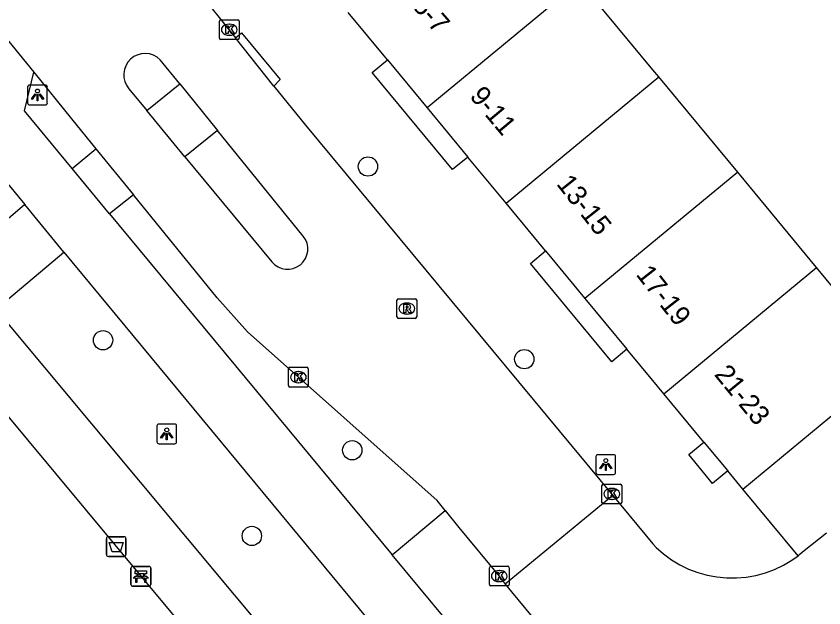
# Model space of a CAD drawing. Extents: x 159280 to 160375, y 384531 to 385872.
# Drawn here: x 159467.75 to 159508.65, y 385108.51 to 385138.49 of the extents above; entities that cross this region are included whole.
import ezdxf

# ---------------------------------------------------------------- set-up
doc = ezdxf.new("R2010")
doc.units = 0
for name, color, linetype in [('IMGEO_Afvalbak', 7, 'Continuous'), ('IMGEO_Bank', 7, 'Continuous'), ('IMGEO_Boom', 7, 'Continuous'), ('IMGEO_Fietspad_open', 7, 'Continuous'), ('IMGEO_Haag', 7, 'Continuous'), ('IMGEO_Kolk', 7, 'Continuous'), ('IMGEO_Lichtpunt', 7, 'Continuous'), ('IMGEO_Pand', 7, 'Continuous'), ('IMGEO_Pand_nummerreeks', 7, 'Continuous'), ('IMGEO_Rijbaan_lokaal_open', 7, 'Continuous'), ('IMGEO_Rioolput', 7, 'Continuous'), ('IMGEO_Voetpad_halfverhard', 7, 'Continuous'), ('IMGEO_Voetpad_open', 7, 'Continuous')]:
    doc.layers.add(name, color=color, linetype=linetype)

msp = doc.modelspace()

# ---------------------------------------------------------------- linework, layer by layer
at = {"layer": 'IMGEO_Afvalbak'}
for p, q in [((159472.423, 385112.112), (159473.213, 385112.112)), ((159473.213, 385112.112), (159472.423, 385112.112)), ((159472.323, 385111.212), (159472.323, 385112.012)), ((159472.323, 385112.012), (159472.323, 385111.212)), ((159473.313, 385112.012), (159473.313, 385111.212)), ((159473.313, 385111.212), (159473.313, 385112.012)), ((159473.213, 385111.112), (159472.423, 385111.112)), ((159472.423, 385111.112), (159473.213, 385111.112))]:
    msp.add_line(p, q, dxfattribs=at)
msp.add_lwpolyline([(159472.466, 385111.826), (159473.17, 385111.826), (159473.021, 385111.356), (159472.615, 385111.356), (159472.466, 385111.826)], dxfattribs=at)
for centre, start, end in [((159472.423, 385112.012), 90, 180), ((159472.423, 385112.012), 90, 180), ((159473.213, 385112.012), 0, 90), ((159473.213, 385112.012), 360, 90), ((159472.423, 385111.212), 180, 270), ((159472.423, 385111.212), 180, 270), ((159473.213, 385111.212), 270, 0), ((159473.213, 385111.212), 270, 0)]:
    msp.add_arc(centre, 0.1, start, end, dxfattribs=at)
at = {"layer": 'IMGEO_Bank'}
for p, q in [((159473.568, 385109.685), (159473.568, 385110.526)), ((159473.568, 385110.526), (159473.568, 385109.685)), ((159473.643, 385110.61), (159474.484, 385110.61)), ((159474.484, 385110.61), (159473.643, 385110.61)), ((159474.568, 385110.535), (159474.568, 385109.694)), ((159474.568, 385109.694), (159474.568, 385110.535)), ((159473.877, 385110.116), (159473.877, 385110.222)), ((159473.921, 385110.222), (159473.921, 385110.116)), ((159474.209, 385110.228), (159473.927, 385110.228)), ((159473.927, 385110.11), (159474.209, 385110.11)), ((159474.215, 385110.116), (159474.215, 385110.222)), ((159474.259, 385110.222), (159474.259, 385110.116)), ((159474.493, 385109.61), (159473.652, 385109.61)), ((159473.652, 385109.61), (159474.493, 385109.61)), ((159474.265, 385110.008), (159473.872, 385110.008))]:
    msp.add_line(p, q, dxfattribs=at)
for points in [[(159473.815, 385110.008), (159473.673, 385110.008), (159473.785, 385110.11), (159473.871, 385110.11)], [(159473.871, 385110.228), (159473.785, 385110.228), (159473.785, 385110.389), (159474.348, 385110.389), (159474.348, 385110.228), (159474.265, 385110.228)], [(159474.265, 385110.11), (159474.348, 385110.11), (159474.46, 385110.008), (159474.321, 385110.008)], [(159473.865, 385110.001), (159473.865, 385109.794), (159473.822, 385109.794), (159473.822, 385110.001)], [(159474.315, 385110.001), (159474.315, 385109.794), (159474.271, 385109.794), (159474.271, 385110.001)]]:
    msp.add_lwpolyline(points, dxfattribs=at)
for centre, radius, start, end in [((159473.646, 385110.532), 0.0779, 92.4484, 184.2845), ((159473.646, 385110.532), 0.0779, 92.4484, 184.2845), ((159474.49, 385110.532), 0.0779, 2.4484, 94.2845), ((159474.49, 385110.532), 0.0779, 2.4484, 94.2845), ((159473.87, 385110.221), 0.00671, 2.8957, 87.1043), ((159473.87, 385110.117), 0.00671, 272.8957, 357.1043), ((159473.927, 385110.221), 0.00671, 92.8957, 177.1043), ((159473.927, 385110.117), 0.00671, 182.8957, 267.1043), ((159474.209, 385110.221), 0.00671, 2.8957, 87.1043), ((159474.209, 385110.117), 0.00671, 272.8957, 357.1043), ((159474.266, 385110.221), 0.00671, 92.8957, 177.1043), ((159474.266, 385110.117), 0.00671, 182.8957, 267.1043), ((159473.646, 385109.688), 0.0779, 182.4484, 274.2845), ((159473.646, 385109.688), 0.0779, 182.4484, 274.2845), ((159473.815, 385110.001), 0.00671, 2.8957, 87.1043), ((159473.872, 385110.001), 0.00671, 92.8957, 177.1043), ((159474.264, 385110.001), 0.00671, 2.8957, 87.1043), ((159474.321, 385110.001), 0.00671, 92.8957, 177.1043), ((159474.49, 385109.688), 0.0779, 272.4484, 4.2845), ((159474.49, 385109.688), 0.0779, 272.4484, 4.2845)]:
    msp.add_arc(centre, radius, start, end, dxfattribs=at)
at = {"layer": 'IMGEO_Boom'}
for centre in [(159485.569, 385130.873), (159472.153, 385122.07), (159493.486, 385121.11), (159484.773, 385116.495), (159479.69, 385112.153)]:
    msp.add_circle(centre, 0.489, dxfattribs=at)
at = {"layer": 'IMGEO_Fietspad_open'}
for points in [[(159405.443, 385221.27), (159417.105, 385196.774), (159421.543, 385188.209), (159424.758, 385182.98), (159430.05, 385175.255), (159434.187, 385170.106), (159442.865, 385159.598), (159444.527, 385157.561), (159454.301, 385145.739), (159456.65, 385142.935), (159463.095, 385135.058), (159465.215, 385132.533), (159468.191, 385128.94)], [(159470.596, 385130.776), (159468.169, 385133.7), (159468.656, 385135.65)], [(159472.473, 385128.474), (159470.596, 385130.776)], [(159470.17, 385126.528), (159468.191, 385128.94)], [(159472.473, 385128.474), (159486.797, 385111.202)], [(159470.17, 385126.528), (159494.306, 385097.36)], [(159499.271, 385101.533), (159496.605, 385099.375), (159486.797, 385111.202)]]:
    msp.add_lwpolyline(points, dxfattribs=at)
at = {"layer": 'IMGEO_Haag'}
msp.add_lwpolyline([(159486.797, 385111.202), (159489.484, 385113.434)], dxfattribs=at)
at = {"layer": 'IMGEO_Kolk'}
for p, q in [((159478.122, 385138.306), (159478.974, 385138.306)), ((159478.047, 385137.38), (159478.047, 385138.232)), ((159478.535, 385138.086), (159478.56, 385138.086)), ((159479.048, 385138.232), (159479.048, 385137.38)), ((159478.558, 385137.526), (159478.533, 385137.526)), ((159478.974, 385137.306), (159478.122, 385137.306)), ((159481.618, 385120.699), (159482.47, 385120.699)), ((159481.543, 385119.773), (159481.543, 385120.625)), ((159482.031, 385120.479), (159482.056, 385120.479)), ((159482.544, 385120.625), (159482.544, 385119.773)), ((159482.054, 385119.919), (159482.029, 385119.919)), ((159482.47, 385119.699), (159481.618, 385119.699)), ((159497.416, 385113.856), (159497.416, 385114.708)), ((159497.491, 385114.782), (159498.343, 385114.782)), ((159497.904, 385114.562), (159497.929, 385114.562)), ((159498.417, 385114.708), (159498.417, 385113.856)), ((159498.343, 385113.782), (159497.491, 385113.782)), ((159497.927, 385114.002), (159497.902, 385114.002)), ((159491.717, 385109.693), (159491.717, 385110.545)), ((159491.792, 385110.619), (159492.644, 385110.619)), ((159492.718, 385110.545), (159492.718, 385109.693)), ((159492.205, 385110.399), (159492.23, 385110.399)), ((159492.644, 385109.619), (159491.792, 385109.619)), ((159492.228, 385109.839), (159492.203, 385109.839))]:
    msp.add_line(p, q, dxfattribs=at)
for points in [[(159478.122, 385138.306), (159478.974, 385138.306)], [(159478.047, 385137.38), (159478.047, 385138.232)], [(159478.368, 385138.006), (159478.491, 385138.006), (159478.491, 385137.855), (159478.621, 385138.006), (159478.785, 385138.006), (159478.639, 385137.855), (159478.792, 385137.606), (159478.64, 385137.606), (159478.555, 385137.77), (159478.491, 385137.703), (159478.491, 385137.606), (159478.368, 385137.606), (159478.368, 385138.006)], [(159479.048, 385138.232), (159479.048, 385137.38)], [(159478.974, 385137.306), (159478.122, 385137.306)], [(159481.618, 385120.699), (159482.47, 385120.699)], [(159481.543, 385119.773), (159481.543, 385120.625)], [(159481.864, 385120.399), (159481.987, 385120.399), (159481.987, 385120.248), (159482.117, 385120.399), (159482.281, 385120.399), (159482.135, 385120.248), (159482.288, 385119.999), (159482.136, 385119.999), (159482.051, 385120.163), (159481.987, 385120.096), (159481.987, 385119.999), (159481.864, 385119.999), (159481.864, 385120.399)], [(159482.544, 385120.625), (159482.544, 385119.773)], [(159482.47, 385119.699), (159481.618, 385119.699)], [(159497.416, 385113.856), (159497.416, 385114.708)], [(159497.491, 385114.782), (159498.343, 385114.782)], [(159498.417, 385114.708), (159498.417, 385113.856)], [(159497.737, 385114.482), (159497.86, 385114.482), (159497.86, 385114.331), (159497.99, 385114.482), (159498.154, 385114.482), (159498.008, 385114.331), (159498.161, 385114.082), (159498.009, 385114.082), (159497.924, 385114.246), (159497.86, 385114.179), (159497.86, 385114.082), (159497.737, 385114.082), (159497.737, 385114.482)], [(159498.343, 385113.782), (159497.491, 385113.782)], [(159491.717, 385109.693), (159491.717, 385110.545)], [(159491.792, 385110.619), (159492.644, 385110.619)], [(159492.718, 385110.545), (159492.718, 385109.693)], [(159492.038, 385110.319), (159492.161, 385110.319), (159492.161, 385110.168), (159492.291, 385110.319), (159492.455, 385110.319), (159492.309, 385110.168), (159492.462, 385109.919), (159492.31, 385109.919), (159492.225, 385110.083), (159492.161, 385110.016), (159492.161, 385109.919), (159492.038, 385109.919), (159492.038, 385110.319)], [(159492.644, 385109.619), (159491.792, 385109.619)]]:
    msp.add_lwpolyline(points, dxfattribs=at)
for centre, start, end in [((159478.124, 385138.23), 91.552, 178.448), ((159478.124, 385138.23), 91.552, 178.448), ((159478.972, 385138.23), 1.552, 88.448), ((159478.972, 385138.23), 1.552, 88.448), ((159478.124, 385137.382), 181.552, 268.448), ((159478.124, 385137.382), 181.552, 268.448), ((159478.972, 385137.382), 271.552, 358.448), ((159478.972, 385137.382), 271.552, 358.448), ((159481.62, 385120.623), 91.552, 178.448), ((159481.62, 385120.623), 91.552, 178.448), ((159482.468, 385120.623), 1.552, 88.448), ((159482.468, 385120.623), 1.552, 88.448), ((159481.62, 385119.775), 181.552, 268.448), ((159481.62, 385119.775), 181.552, 268.448), ((159482.468, 385119.775), 271.552, 358.448), ((159482.468, 385119.775), 271.552, 358.448), ((159497.493, 385114.706), 91.552, 178.448), ((159497.493, 385114.706), 91.552, 178.448), ((159498.341, 385114.706), 1.552, 88.448), ((159498.341, 385114.706), 1.552, 88.448), ((159497.493, 385113.858), 181.552, 268.448), ((159497.493, 385113.858), 181.552, 268.448), ((159498.341, 385113.858), 271.552, 358.448), ((159498.341, 385113.858), 271.552, 358.448), ((159491.794, 385110.543), 91.552, 178.448), ((159491.794, 385110.543), 91.552, 178.448), ((159492.642, 385110.543), 1.552, 88.448), ((159492.642, 385110.543), 1.552, 88.448), ((159491.794, 385109.695), 181.552, 268.448), ((159491.794, 385109.695), 181.552, 268.448), ((159492.642, 385109.695), 271.552, 358.448), ((159492.642, 385109.695), 271.552, 358.448)]:
    msp.add_arc(centre, 0.0765, start, end, dxfattribs=at)
for centre, major_axis, ratio, start_param, end_param in [((159478.534, 385137.806), (-0.387, 0.002), 0.722429, 4.712389, 7.853982), ((159478.559, 385137.806), (-0.39, 0.002), 0.717154, 1.570796, 4.712389), ((159482.03, 385120.199), (-0.387, 0.002), 0.722429, 4.712389, 7.853982), ((159482.055, 385120.199), (-0.39, 0.002), 0.717154, 1.570796, 4.712389), ((159497.903, 385114.282), (-0.387, 0.002), 0.722429, 4.712389, 7.853982), ((159497.928, 385114.282), (-0.39, 0.002), 0.717154, 1.570796, 4.712389), ((159492.204, 385110.119), (-0.387, 0.002), 0.722429, 4.712389, 7.853982), ((159492.229, 385110.119), (-0.39, 0.002), 0.717154, 1.570796, 4.712389)]:
    msp.add_ellipse(centre, major_axis=major_axis, ratio=ratio, start_param=start_param, end_param=end_param, dxfattribs=at)
at = {"layer": 'IMGEO_Lichtpunt'}
for p, q in [((159469.238, 385134.995), (159468.43, 385134.995)), ((159469.238, 385134.995), (159468.43, 385134.995)), ((159468.336, 385134.9), (159468.336, 385134.093)), ((159468.336, 385134.9), (159468.336, 385134.093)), ((159469.332, 385134.093), (159469.332, 385134.9)), ((159469.332, 385134.093), (159469.332, 385134.9)), ((159468.43, 385133.999), (159469.238, 385133.999)), ((159468.43, 385133.999), (159469.238, 385133.999)), ((159475.784, 385117.822), (159474.976, 385117.822)), ((159475.784, 385117.822), (159474.976, 385117.822)), ((159474.882, 385117.727), (159474.882, 385116.92)), ((159474.882, 385117.727), (159474.882, 385116.92)), ((159475.878, 385116.92), (159475.878, 385117.727)), ((159475.878, 385116.92), (159475.878, 385117.727)), ((159474.976, 385116.826), (159475.784, 385116.826)), ((159474.976, 385116.826), (159475.784, 385116.826)), ((159497.115, 385116.176), (159497.115, 385115.369)), ((159497.115, 385116.176), (159497.115, 385115.369)), ((159498.017, 385116.271), (159497.209, 385116.271)), ((159498.017, 385116.271), (159497.209, 385116.271)), ((159498.111, 385115.369), (159498.111, 385116.176)), ((159498.111, 385115.369), (159498.111, 385116.176)), ((159497.209, 385115.275), (159498.017, 385115.275)), ((159497.209, 385115.275), (159498.017, 385115.275))]:
    msp.add_line(p, q, dxfattribs=at)
for points in [[(159468.71, 385134.564), (159468.749, 385134.536), (159468.561, 385134.274), (159468.523, 385134.301), (159468.71, 385134.564)], [(159468.922, 385134.536), (159468.96, 385134.563), (159469.147, 385134.301), (159469.108, 385134.273), (159468.922, 385134.536)], [(159468.812, 385134.516), (159468.859, 385134.516), (159468.859, 385134.194), (159468.812, 385134.194), (159468.812, 385134.516)], [(159475.256, 385117.391), (159475.295, 385117.363), (159475.107, 385117.101), (159475.069, 385117.128), (159475.256, 385117.391)], [(159475.468, 385117.363), (159475.506, 385117.39), (159475.693, 385117.128), (159475.654, 385117.1), (159475.468, 385117.363)], [(159475.358, 385117.343), (159475.405, 385117.343), (159475.405, 385117.021), (159475.358, 385117.021), (159475.358, 385117.343)], [(159497.489, 385115.84), (159497.528, 385115.812), (159497.34, 385115.55), (159497.302, 385115.577), (159497.489, 385115.84)], [(159497.591, 385115.792), (159497.638, 385115.792), (159497.638, 385115.47), (159497.591, 385115.47), (159497.591, 385115.792)], [(159497.701, 385115.812), (159497.739, 385115.839), (159497.926, 385115.577), (159497.887, 385115.549), (159497.701, 385115.812)]]:
    msp.add_lwpolyline(points, dxfattribs=at)
for centre in [(159468.835, 385134.698), (159475.381, 385117.525), (159497.614, 385115.974)]:
    msp.add_circle(centre, 0.0994, dxfattribs=at)
for centre, start, end in [((159468.43, 385134.9), 90, 180), ((159468.43, 385134.9), 90, 180), ((159469.238, 385134.9), 0, 90), ((159469.238, 385134.9), 0, 90), ((159468.43, 385134.093), 180, 270), ((159468.43, 385134.093), 180, 270), ((159469.238, 385134.093), 270, 0), ((159469.238, 385134.093), 270, 360), ((159474.976, 385117.727), 90, 180), ((159474.976, 385117.727), 90, 180), ((159475.784, 385117.727), 0, 90), ((159475.784, 385117.727), 0, 90), ((159474.976, 385116.92), 180, 270), ((159474.976, 385116.92), 180, 270), ((159475.784, 385116.92), 270, 0), ((159475.784, 385116.92), 270, 360), ((159497.209, 385116.176), 90, 180), ((159497.209, 385116.176), 90, 180), ((159498.017, 385116.176), 0, 90), ((159498.017, 385116.176), 0, 90), ((159497.209, 385115.369), 180, 270), ((159497.209, 385115.369), 180, 270), ((159498.017, 385115.369), 270, 0), ((159498.017, 385115.369), 270, 360)]:
    msp.add_arc(centre, 0.0946, start, end, dxfattribs=at)
at = {"layer": 'IMGEO_Pand'}
for points in [[(159496.296, 385140.25), (159488.561, 385133.849)], [(159500.294, 385135.42), (159500, 385135.775), (159496.296, 385140.25)], [(159486.552, 385136.277), (159484.564, 385138.679)], [(159486.552, 385136.277), (159488.561, 385133.849)], [(159492.559, 385129.019), (159500.294, 385135.42)], [(159504.291, 385130.59), (159500.294, 385135.42)], [(159488.561, 385133.849), (159490.626, 385131.354)], [(159492.559, 385129.019), (159490.626, 385131.354)], [(159504.291, 385130.59), (159496.556, 385124.189)], [(159508.288, 385125.76), (159504.291, 385130.59)], [(159494.566, 385126.593), (159492.559, 385129.019)], [(159494.566, 385126.593), (159496.556, 385124.189)], [(159500.553, 385119.359), (159508.288, 385125.76)], [(159509.932, 385118.983), (159512.285, 385120.93), (159508.288, 385125.76)], [(159496.556, 385124.189), (159498.685, 385121.616)], [(159500.553, 385119.359), (159500, 385120.027), (159498.685, 385121.616)], [(159502.58, 385116.909), (159500.553, 385119.359)], [(159504.55, 385114.528), (159509.932, 385118.983)], [(159502.58, 385116.909), (159503.785, 385115.453)], [(159504.55, 385114.528), (159503.785, 385115.453)]]:
    msp.add_lwpolyline(points, dxfattribs=at)
at = {"layer": 'IMGEO_Rijbaan_lokaal_open'}
for points in [[(159476.853, 385139.918), (159478.861, 385137.393)], [(159466.777, 385137.938), (159468.656, 385135.65)], [(159480.804, 385134.95), (159478.861, 385137.393)], [(159476.044, 385135.056), (159475.053, 385136.278)], [(159468.656, 385135.65), (159470.552, 385133.285), (159471.786, 385131.774)], [(159476.044, 385135.056), (159477.948, 385132.706)], [(159473.462, 385134.813), (159474.367, 385133.716)], [(159480.804, 385134.95), (159482.4, 385132.975), (159497.976, 385114.2)], [(159476.303, 385131.369), (159474.367, 385133.716)], [(159482.295, 385127.343), (159477.948, 385132.706)], [(159471.786, 385131.774), (159473.693, 385129.437)], [(159476.303, 385131.369), (159480.7, 385126.039)], [(159489.484, 385113.434), (159489.068, 385113.942), (159479.463, 385122.501), (159477.933, 385124.218), (159473.693, 385129.437)], [(159497.976, 385114.2), (159492.52, 385109.714)], [(159497.976, 385114.2), (159500, 385111.761), (159500.161, 385111.567), (159500.534, 385111.239), (159500.935, 385110.947), (159501.361, 385110.691), (159501.808, 385110.475), (159502.273, 385110.299), (159502.751, 385110.165), (159503.239, 385110.075), (159503.733, 385110.029), (159504.23, 385110.027), (159504.725, 385110.069), (159505.214, 385110.156), (159505.693, 385110.285), (159506.159, 385110.458), (159506.608, 385110.671), (159507.035, 385110.923), (159507.347, 385111.146)], [(159489.484, 385113.434), (159490.177, 385112.587), (159492.219, 385110.121), (159492.52, 385109.714)], [(159508.785, 385112.295), (159507.575, 385111.323), (159507.439, 385111.212), (159507.347, 385111.146)], [(159492.52, 385109.714), (159499.271, 385101.533)]]:
    msp.add_lwpolyline(points, dxfattribs=at)
for centre, radius, start, end in [((159474.282, 385135.519), 1.082, 44.5448, 220.7332), ((159481.495, 385126.694), 1.03, 219.5071, 39.0287)]:
    msp.add_arc(centre, radius, start, end, dxfattribs=at)
at = {"layer": 'IMGEO_Rioolput'}
for p, q in [((159487.035, 385123.25), (159487.035, 385124.102)), ((159487.11, 385124.176), (159487.962, 385124.176)), ((159487.523, 385123.956), (159487.548, 385123.956)), ((159488.036, 385124.102), (159488.036, 385123.25)), ((159487.962, 385123.176), (159487.11, 385123.176)), ((159487.546, 385123.396), (159487.521, 385123.396))]:
    msp.add_line(p, q, dxfattribs=at)
for points in [[(159487.035, 385123.25), (159487.035, 385124.102)], [(159487.11, 385124.176), (159487.962, 385124.176)], [(159488.036, 385124.102), (159488.036, 385123.25)], [(159487.624, 385123.874), (159487.372, 385123.876), (159487.372, 385123.476)], [(159487.372, 385123.476), (159487.496, 385123.476), (159487.496, 385123.638), (159487.507, 385123.638)], [(159487.55, 385123.795), (159487.496, 385123.795), (159487.496, 385123.714)], [(159487.496, 385123.714), (159487.548, 385123.714)], [(159487.554, 385123.609), (159487.625, 385123.476), (159487.765, 385123.476), (159487.7, 385123.602)], [(159487.962, 385123.176), (159487.11, 385123.176)]]:
    msp.add_lwpolyline(points, dxfattribs=at)
for centre, radius, start, end in [((159487.112, 385124.1), 0.0765, 91.552, 178.448), ((159487.112, 385124.1), 0.0765, 91.552, 178.448), ((159487.96, 385124.1), 0.0765, 1.552, 88.448), ((159487.96, 385124.1), 0.0765, 1.552, 88.448), ((159487.506, 385123.585), 0.0533, 26.0293, 88.6989), ((159487.532, 385123.903), 0.19, 274.7715, 282.9687), ((159487.556, 385123.699), 0.0964, 77.0061, 93.1865), ((159487.57, 385123.756), 0.0378, 276.6634, 79.6772), ((159487.623, 385123.764), 0.109, 350.3612, 89.416), ((159487.621, 385123.764), 0.112, 277.5842, 350.9817), ((159487.605, 385123.549), 0.108, 29.5134, 73.7905), ((159487.112, 385123.252), 0.0765, 181.552, 268.448), ((159487.112, 385123.252), 0.0765, 181.552, 268.448), ((159487.96, 385123.252), 0.0765, 271.552, 358.448), ((159487.96, 385123.252), 0.0765, 271.552, 358.448)]:
    msp.add_arc(centre, radius, start, end, dxfattribs=at)
for centre, major_axis, ratio, start_param, end_param in [((159487.522, 385123.676), (-0.387, 0.002), 0.722429, 4.712389, 7.853982), ((159487.547, 385123.676), (-0.39, 0.002), 0.717154, 1.570796, 4.712389)]:
    msp.add_ellipse(centre, major_axis=major_axis, ratio=ratio, start_param=start_param, end_param=end_param, dxfattribs=at)
at = {"layer": 'IMGEO_Voetpad_halfverhard'}
for points in [[(159468.191, 385128.94), (159464.844, 385126.096), (159443.614, 385151.741), (159437.266, 385159.621), (159427.107, 385172.032), (159421.69, 385179.755)], [(159440.526, 385150.679), (159453.908, 385134.35), (159462.304, 385124.254), (159489.188, 385091.93)], [(159494.306, 385097.36), (159490.959, 385094.592), (159466.718, 385123.644), (159470.17, 385126.528)]]:
    msp.add_lwpolyline(points, dxfattribs=at)
at = {"layer": 'IMGEO_Voetpad_open'}
for points in [[(159478.861, 385137.393), (159479.169, 385137.647), (159481.128, 385135.274), (159480.804, 385134.95)], [(159490.626, 385131.354), (159489.856, 385130.717), (159485.782, 385135.64), (159486.552, 385136.277)], [(159474.367, 385133.716), (159476.044, 385135.056)], [(159477.948, 385132.706), (159476.303, 385131.369)], [(159470.596, 385130.776), (159471.786, 385131.774)], [(159473.693, 385129.437), (159472.473, 385128.474)], [(159498.685, 385121.616), (159497.915, 385120.979), (159493.796, 385125.956), (159494.566, 385126.593)], [(159503.785, 385115.453), (159503.015, 385114.816), (159501.81, 385116.272), (159502.58, 385116.909)], [(159507.347, 385111.146), (159504.55, 385114.528)]]:
    msp.add_lwpolyline(points, dxfattribs=at)

# ---------------------------------------------------------------- texts
at = {"layer": 'IMGEO_Pand_nummerreeks'}
for s, rotation, p in [('5-7', 311.1382, (159487.772, 385138.987)), ('9-11', 309.9349, (159490.679, 385134.416)), ('13-15', 308.4166, (159495.078, 385129.978)), ('17-19', 308.1015, (159499.105, 385125.396)), ('21-23', 309.3276, (159503.068, 385120.322))]:
    msp.add_text(s, height=1, rotation=rotation, dxfattribs=at).set_placement(p)

doc.saveas('drawing.dxf')
